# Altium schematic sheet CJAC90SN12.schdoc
size 127 x 101 mm
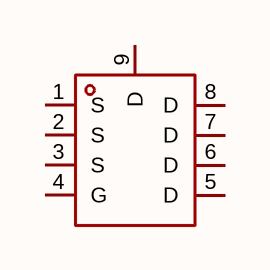
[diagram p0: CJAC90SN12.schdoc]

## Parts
Q?  cjac90sn12  [PDFN-8_L5.8-W4.9-P1.27-LS6.1-BL-A]  (value not drawn)

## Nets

Not connected (* = marked no-connect by the designer): Q? 1(S) 2(S) 3(S) 4(G) 5(D) 6(D) 7(D) 8(D) 9(D)

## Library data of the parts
Q? = cjac90sn12: 数量:1个N沟道;漏源电压(Vdss):120V;连续漏极电流(Id):90A;导通电阻(RDS(on)):5.4mΩ@10V;耗散功率(Pd):2W;阈值电压(Vgs(th)):4V;; Manufacturer: CJ(江苏长电/长晶); AddInBom: yes; ModelId: 450a83d8ea544a1683b51becadb75d8a; ModelTransform: 200.787,238.189,0,0,0,0,-0.005,0.003,0; Number: 1个N沟道; Drain to Source Voltage: 120V; Current - Continuous Drain(Id): 90A; Pd - Power Dissipation: 2W; Gate Threshold Voltage (Vgs(th)): 4V; Gate Charge(Qg): 45.2nC; Input Capacitance(Ciss): 3.67nF; Reverse Transfer Capacitance (Crss@Vds): 7.6pF; Type: N沟道; Output Capacitance(Coss): 472pF; Vgs: ±20V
